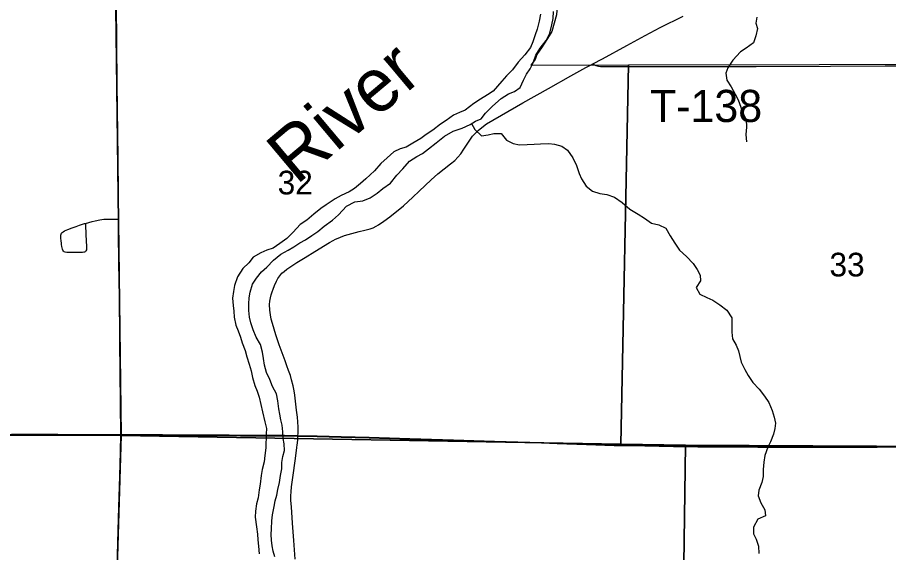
# Model space of a CAD drawing. Extents: x 0 to 34, y 0 to 22.
# Drawn here: x 4.194 to 4.964, y 17.65 to 18.123 of the extents above; entities that cross this region are included whole.
import ezdxf

# ---------------------------------------------------------------- set-up
doc = ezdxf.new("R2010")
doc.units = 0
for name, color, linetype in [('GM_X_Corporation', 7, 'Continuous'), ('GM_X_County_Road', 7, 'Continuous'), ('GM_X_Major_River', 7, 'Continuous'), ('GM_X_Major_River_Text', 7, 'Continuous'), ('GM_X_Minor_River', 7, 'Continuous'), ('GM_X_Section_Text', 7, 'Continuous'), ('GM_X_State_Route', 7, 'Continuous'), ('GM_X_Township_Road', 7, 'Continuous'), ('GM_X_Township_Road_Text', 7, 'Continuous')]:
    doc.layers.add(name, color=color, linetype=linetype)

msp = doc.modelspace()

# ---------------------------------------------------------------- linework, layer by layer
at = {"layer": 'GM_X_Corporation'}
for points in [[(3.77934, 18.25611), (4.27934, 18.22655), (4.28542, 17.75394), (3.7492, 17.7546)], [(4.27934, 18.22655), (4.66117, 18.20518), (4.66186, 18.19617), (4.66594, 18.18364), (4.67032, 18.16257), (4.67175, 18.15081), (4.67108, 18.13774), (4.67023, 18.12562), (4.66614, 18.11087), (4.66231, 18.10465), (4.65694, 18.09654), (4.65291, 18.09051), (4.65118, 18.08635), (4.64735, 18.08108), (4.73395, 18.08156), (4.72704, 17.74623), (4.28542, 17.75394)], [(5.2393, 18.08245), (5.23463, 17.74294), (4.78425, 17.74522), (4.72704, 17.74623), (4.73395, 18.08156)], [(4.28542, 17.75394), (4.27027, 17.25592), (3.73479, 17.25336), (3.7492, 17.7546)], [(4.72704, 17.74623), (4.78425, 17.74522), (4.77754, 17.26078), (4.56251, 17.2645), (4.54557, 17.25477), (4.27027, 17.25592), (4.28542, 17.75394)], [(5.26362, 17.74328), (5.26124, 17.2552), (4.77754, 17.26078), (4.78425, 17.74522), (5.23463, 17.74294)]]:
    msp.add_lwpolyline(points, close=True, dxfattribs=at)
for points in [[(4.97619, 17.74408), (4.9535, 17.74392), (4.942, 17.74382), (4.92615, 17.74385), (4.90564, 17.74379), (4.89569, 17.74385), (4.88201, 17.74392), (4.85995, 17.74394), (4.84814, 17.74397), (4.82265, 17.74401), (4.79499, 17.74422), (4.77354, 17.7445), (4.7608, 17.74479), (4.73563, 17.74518), (4.72103, 17.74543), (4.69648, 17.74623), (4.6707, 17.74707), (4.65704, 17.74753), (4.61541, 17.74867), (4.57907, 17.74986), (4.54056, 17.75104), (4.50452, 17.752), (4.47972, 17.75262), (4.4586, 17.7532), (4.4415, 17.75361), (4.4407, 17.75363), (4.42966, 17.75376), (4.41728, 17.75392), (4.40734, 17.75394), (4.39708, 17.75395), (4.39056, 17.75398), (4.38063, 17.75406), (4.3645, 17.75417), (4.35332, 17.75426), (4.33872, 17.75431), (4.32194, 17.75441), (4.29335, 17.75456), (4.28484, 17.75461), (4.27337, 17.75456), (4.25326, 17.75451), (4.24034, 17.75448), (4.22915, 17.75469), (4.20335, 17.75483), (4.18875, 17.75498)], [(4.18875, 17.75498), (4.20335, 17.75483), (4.22915, 17.75469), (4.24034, 17.75448), (4.25326, 17.75451), (4.27337, 17.75456), (4.28484, 17.75461), (4.29335, 17.75456), (4.32194, 17.75441), (4.33872, 17.75431), (4.35332, 17.75426), (4.3645, 17.75417), (4.38063, 17.75406), (4.39056, 17.75398), (4.39708, 17.75395), (4.40734, 17.75394), (4.41728, 17.75392), (4.42966, 17.75376), (4.4407, 17.75363), (4.4415, 17.75361), (4.4586, 17.7532), (4.47972, 17.75262), (4.50452, 17.752), (4.54056, 17.75104), (4.57907, 17.74986), (4.61541, 17.74867), (4.65704, 17.74753), (4.6707, 17.74707), (4.69648, 17.74623), (4.72103, 17.74543), (4.73563, 17.74518), (4.7608, 17.74479), (4.77354, 17.7445), (4.79499, 17.74422), (4.82265, 17.74401), (4.84814, 17.74397), (4.85995, 17.74394), (4.88201, 17.74392), (4.89569, 17.74385), (4.90564, 17.74379), (4.92615, 17.74385), (4.942, 17.74382), (4.9535, 17.74392), (4.97619, 17.74408)]]:
    msp.add_lwpolyline(points, dxfattribs=at)
at = {"layer": 'GM_X_County_Road'}
for points in [[(4.70234, 18.08224), (4.71083, 18.08667), (4.73233, 18.09849), (4.74868, 18.10747), (4.76188, 18.11443), (4.78217, 18.1246)], [(4.44161, 17.75333), (4.44165, 17.75625), (4.44172, 17.76119), (4.44148, 17.76581), (4.44105, 17.77014), (4.44044, 17.7763), (4.43951, 17.78433), (4.43882, 17.78955), (4.43823, 17.79322), (4.43733, 17.79777), (4.43601, 17.80318), (4.43487, 17.80703), (4.43335, 17.81142), (4.43186, 17.8155), (4.43022, 17.81986), (4.42845, 17.8245), (4.42672, 17.82916), (4.4249, 17.83413), (4.42336, 17.83854), (4.42191, 17.84297), (4.42042, 17.84772), (4.41902, 17.85283), (4.41802, 17.85676), (4.41728, 17.86044), (4.41661, 17.86472), (4.41644, 17.86974), (4.41677, 17.8727), (4.41718, 17.8755), (4.41792, 17.87829), (4.41874, 17.88093), (4.41965, 17.88323), (4.42096, 17.8866), (4.42261, 17.89022), (4.42384, 17.89261), (4.42548, 17.89507), (4.42746, 17.8973), (4.42926, 17.8989), (4.43165, 17.90083), (4.43432, 17.90262), (4.43782, 17.9049), (4.44059, 17.9067), (4.44805, 17.91117), (4.4565, 17.91641), (4.46944, 17.92439), (4.47268, 17.92624), (4.47474, 17.92741), (4.47704, 17.92839), (4.47934, 17.9293), (4.48267, 17.93058), (4.48921, 17.93243), (4.49571, 17.93407), (4.50072, 17.93523), (4.50541, 17.93654), (4.50821, 17.93753), (4.51059, 17.93877), (4.51289, 17.94016), (4.51742, 17.94321), (4.52276, 17.94727), (4.53486, 17.95684), (4.54302, 17.96442), (4.54885, 17.96996), (4.5594, 17.97995), (4.56536, 17.9852), (4.5764, 17.99387), (4.58016, 17.99708), (4.58301, 17.99989), (4.58556, 18.00295), (4.58835, 18.007), (4.59341, 18.01481), (4.59602, 18.01833), (4.59849, 18.02116), (4.60097, 18.02355), (4.60411, 18.02615), (4.60842, 18.02926), (4.64031, 18.04789), (4.66306, 18.06069), (4.68287, 18.07178), (4.69626, 18.07899), (4.70091, 18.08149), (4.70234, 18.08224)], [(3.74899, 17.75688), (3.77002, 17.75675), (3.79458, 17.75662), (3.8353, 17.75664), (3.84803, 17.75657), (3.86264, 17.75646), (3.90025, 17.75626), (3.95402, 17.75601), (3.99287, 17.75558), (4.02768, 17.75539), (4.09315, 17.75516), (4.11614, 17.75508), (4.12764, 17.75505), (4.13167, 17.75508), (4.14442, 17.75492), (4.1584, 17.7548), (4.17301, 17.75462), (4.18887, 17.75471), (4.20346, 17.75455), (4.22926, 17.75441), (4.24045, 17.7542), (4.25337, 17.75423), (4.27348, 17.75428), (4.28495, 17.75434)], [(4.28495, 17.75434), (4.29346, 17.75429), (4.32205, 17.75413), (4.33883, 17.75404), (4.35344, 17.75398), (4.36461, 17.75389), (4.38074, 17.75378), (4.39067, 17.7537), (4.3972, 17.75367), (4.40745, 17.75367), (4.41739, 17.75364), (4.42977, 17.75349), (4.44082, 17.75335), (4.44161, 17.75333)], [(4.44161, 17.75333), (4.45871, 17.75292), (4.47983, 17.75234), (4.50463, 17.75172), (4.54067, 17.75076), (4.57919, 17.74959), (4.61553, 17.7484), (4.65715, 17.74726), (4.67081, 17.74679), (4.69659, 17.74595), (4.72114, 17.74515), (4.73574, 17.7449), (4.76091, 17.74451), (4.77366, 17.74422), (4.7951, 17.74394), (4.82277, 17.74374), (4.84825, 17.7437), (4.86006, 17.74366), (4.88212, 17.74365), (4.8958, 17.74357), (4.90575, 17.74352), (4.92626, 17.74357), (4.94211, 17.74354), (4.95361, 17.74365), (4.9763, 17.7438)]]:
    msp.add_lwpolyline(points, dxfattribs=at)
at = {"layer": 'GM_X_Major_River'}
for points in [[(4.65613, 18.12639), (4.65496, 18.12013), (4.65321, 18.11312), (4.65128, 18.10801), (4.64935, 18.10175), (4.64723, 18.09683), (4.64208, 18.09041), (4.63636, 18.0838), (4.6312, 18.077), (4.62605, 18.0719), (4.62185, 18.06699), (4.61422, 18.0583), (4.60928, 18.05511), (4.603, 18.05116), (4.59711, 18.0474), (4.5893, 18.04137), (4.58437, 18.0395), (4.57924, 18.03687), (4.57277, 18.03216), (4.56764, 18.02916), (4.56078, 18.02369), (4.55508, 18.01993), (4.55032, 18.01635), (4.5431, 18.01222), (4.5372, 18.00884), (4.53189, 18.00735), (4.52638, 18.00453), (4.52048, 17.99944), (4.51476, 17.99416), (4.50923, 17.98774), (4.50161, 17.98076), (4.49685, 17.97661), (4.49152, 17.97228), (4.48676, 17.96927), (4.47992, 17.96589), (4.47441, 17.96308), (4.46661, 17.95781), (4.46167, 17.95442), (4.45558, 17.94952), (4.44929, 17.94406), (4.44359, 17.94029), (4.43748, 17.9335), (4.43177, 17.92802), (4.42568, 17.9235), (4.41978, 17.91955), (4.41409, 17.91769), (4.40877, 17.91544), (4.40212, 17.9115), (4.39811, 17.90658), (4.39277, 17.90149), (4.38818, 17.89411), (4.38548, 17.88635), (4.3845, 17.88104), (4.38371, 17.87516), (4.38423, 17.86889), (4.38477, 17.86376), (4.3853, 17.85844), (4.38659, 17.85141), (4.38864, 17.84647), (4.39087, 17.84076), (4.39236, 17.83581), (4.39497, 17.82915), (4.39645, 17.82326), (4.39849, 17.81679), (4.40016, 17.8109), (4.40145, 17.8052), (4.40348, 17.79797), (4.40554, 17.79302), (4.40721, 17.7877)], [(4.4293, 17.74638), (4.42857, 17.75132), (4.42823, 17.75701), (4.4277, 17.7629), (4.42659, 17.76765), (4.42548, 17.77259), (4.42457, 17.77735), (4.42366, 17.78437), (4.42257, 17.79084), (4.41901, 17.79731), (4.41659, 17.8034), (4.41379, 17.80968), (4.41212, 17.81595), (4.41102, 17.82204), (4.41011, 17.82755), (4.40845, 17.83439), (4.4047, 17.84086), (4.4019, 17.84734), (4.39986, 17.85342), (4.39875, 17.85836), (4.39803, 17.86444), (4.39807, 17.87014), (4.39848, 17.87564), (4.39946, 17.88057), (4.4014, 17.88777), (4.40503, 17.89306), (4.40923, 17.89854), (4.41399, 17.90269), (4.42009, 17.90892), (4.42638, 17.9142), (4.43284, 17.91777), (4.43797, 17.92059), (4.4433, 17.92416), (4.44824, 17.92679), (4.45394, 17.93055), (4.45908, 17.93413), (4.46479, 17.93903), (4.47202, 17.9443), (4.47754, 17.94902), (4.4846, 17.95657), (4.49182, 17.96032), (4.49883, 17.96142), (4.50548, 17.96385), (4.51176, 17.96818), (4.51671, 17.97232), (4.52355, 17.97703), (4.52909, 17.98402), (4.53443, 17.98949), (4.54034, 17.99648), (4.54662, 18.00043), (4.55175, 18.00306), (4.55708, 18.0072), (4.56393, 18.01248), (4.57117, 18.01851), (4.57877, 18.02283), (4.58674, 18.02563), (4.59377, 18.02881), (4.59852, 18.03182), (4.60346, 18.03388), (4.60747, 18.03879), (4.61357, 18.04502), (4.62119, 18.05162), (4.62785, 18.05595), (4.63316, 18.058), (4.63792, 18.06139), (4.64099, 18.06783), (4.64367, 18.07313), (4.64693, 18.07804), (4.64942, 18.08334), (4.65193, 18.09016), (4.65575, 18.09621), (4.66091, 18.10301), (4.66417, 18.10945), (4.66611, 18.11684), (4.6671, 18.12253), (4.66751, 18.1286)], [(4.40721, 17.7877), (4.40887, 17.78123), (4.41035, 17.77477), (4.41219, 17.76603), (4.41366, 17.76013), (4.41345, 17.75539), (4.41318, 17.74286), (4.41238, 17.73622), (4.41158, 17.73053), (4.41003, 17.7239), (4.40905, 17.71859), (4.40824, 17.71081), (4.40726, 17.70588), (4.40627, 17.69886), (4.40491, 17.69356), (4.40412, 17.68711), (4.40389, 17.6816), (4.40497, 17.67305), (4.40569, 17.66659), (4.40604, 17.66166), (4.40657, 17.65615), (4.40729, 17.64931)], [(4.4211, 17.64676), (4.41961, 17.65152), (4.4187, 17.65646), (4.41816, 17.6614), (4.41781, 17.66652), (4.41822, 17.67127), (4.41846, 17.67848), (4.41906, 17.68379), (4.42043, 17.691), (4.42141, 17.69612), (4.42295, 17.70123), (4.42374, 17.70616), (4.4253, 17.71242), (4.42628, 17.71849), (4.42727, 17.72437), (4.4273, 17.72987), (4.42809, 17.73518), (4.42964, 17.74068), (4.4293, 17.74638)]]:
    msp.add_lwpolyline(points, dxfattribs=at)
at = {"layer": 'GM_X_Minor_River'}
for points in [[(4.84741, 18.12356), (4.84643, 18.11825), (4.84791, 18.11349), (4.84636, 18.10705), (4.84443, 18.10099), (4.83796, 18.09609), (4.83301, 18.09289), (4.82615, 18.08572), (4.82175, 18.07891), (4.81982, 18.07399), (4.82092, 18.06791), (4.82448, 18.06219), (4.82823, 18.05553), (4.83066, 18.05058), (4.83308, 18.04411), (4.83494, 18.03897), (4.83774, 18.03307), (4.83808, 18.02643), (4.83766, 18.01979), (4.83819, 18.01333)], [(4.59505, 18.02962), (4.59791, 18.02423), (4.60394, 18.01888), (4.60981, 18.01961), (4.61474, 18.02091), (4.62137, 18.02087), (4.62588, 18.01496), (4.63173, 18.01208), (4.63741, 18.01071), (4.64423, 18.01106), (4.65048, 18.0114), (4.65616, 18.01174), (4.66336, 18.01208), (4.66847, 18.01129), (4.6749, 18.00955), (4.6798, 18.0061), (4.68468, 17.99924), (4.68786, 17.99258), (4.69028, 17.98554), (4.69233, 17.98078), (4.69627, 17.9743), (4.70211, 17.96971), (4.70854, 17.96778), (4.71478, 17.96679), (4.72159, 17.96447), (4.72819, 17.95969), (4.73516, 17.95395), (4.74232, 17.94936), (4.74799, 17.9461), (4.75421, 17.9415), (4.76064, 17.94014), (4.76687, 17.93706), (4.7708, 17.93021), (4.77474, 17.92392), (4.77906, 17.91763), (4.78508, 17.91209), (4.79091, 17.90579), (4.79467, 17.90045), (4.79729, 17.89569), (4.79745, 17.89057), (4.79381, 17.8847), (4.79699, 17.8788), (4.80323, 17.87573), (4.80832, 17.87342), (4.81455, 17.8694), (4.82077, 17.86461), (4.82527, 17.85775), (4.82519, 17.84523), (4.82572, 17.83934), (4.8291, 17.83381), (4.83115, 17.82868), (4.83226, 17.82373), (4.83355, 17.81879), (4.83673, 17.81213), (4.83954, 17.80698), (4.84366, 17.8007), (4.8495, 17.79497), (4.8542, 17.78868), (4.85795, 17.78296), (4.86074, 17.77592), (4.8626, 17.77002), (4.86371, 17.76489), (4.86311, 17.76015), (4.86213, 17.75503), (4.85925, 17.7484), (4.85713, 17.74348), (4.85443, 17.73609), (4.85345, 17.73021), (4.85303, 17.72395), (4.8528, 17.71769), (4.85163, 17.71238), (4.84913, 17.70556), (4.84834, 17.70044), (4.85076, 17.69435), (4.85432, 17.68806), (4.85486, 17.68294), (4.84821, 17.67994), (4.84438, 17.67294), (4.84434, 17.66705), (4.84677, 17.66229), (4.84882, 17.65601), (4.84897, 17.64956)]]:
    msp.add_lwpolyline(points, dxfattribs=at)
at = {"layer": 'GM_X_State_Route'}
for points in [[(4.28495, 17.75434), (4.2847, 17.78307), (4.28404, 17.83703), (4.28368, 17.88024), (4.28332, 17.90541), (4.28302, 17.93431), (4.28296, 17.94523), (4.28283, 17.96757), (4.28248, 17.99926), (4.28234, 18.02008), (4.28186, 18.06515), (4.28154, 18.09965), (4.28121, 18.13602)], [(4.28202, 17.64809), (4.2827, 17.66981), (4.28329, 17.69063), (4.28395, 17.71797), (4.28455, 17.73939), (4.28495, 17.75434)]]:
    msp.add_lwpolyline(points, dxfattribs=at)
at = {"layer": 'GM_X_Township_Road'}
for points in [[(4.70234, 18.08224), (4.70329, 18.08175), (4.70501, 18.08093), (4.70723, 18.08035), (4.70921, 18.08003), (4.71118, 18.08003), (4.71783, 18.07988), (4.75078, 18.08005), (4.79119, 18.08008), (4.84683, 18.08013), (4.91242, 18.08026), (4.96091, 18.08054), (4.9927, 18.0806)], [(4.25371, 17.94132), (4.25379, 17.9389), (4.25386, 17.93691), (4.25394, 17.93471), (4.2541, 17.93161), (4.25464, 17.92074), (4.25466, 17.91888), (4.25452, 17.91796), (4.25416, 17.9171), (4.25379, 17.91661), (4.25332, 17.91621), (4.25276, 17.91594), (4.25217, 17.91577), (4.25094, 17.91563), (4.24628, 17.91568), (4.23944, 17.91564), (4.23725, 17.91566), (4.23572, 17.91587), (4.23487, 17.91623), (4.23417, 17.91679), (4.23365, 17.91755), (4.23332, 17.91843), (4.23303, 17.91964), (4.23288, 17.92085), (4.23266, 17.92269), (4.2325, 17.9239), (4.23221, 17.92593), (4.23186, 17.9284), (4.23179, 17.92995), (4.23188, 17.93088), (4.23213, 17.93177), (4.23255, 17.9326), (4.23314, 17.93332), (4.23387, 17.93388), (4.23524, 17.93463), (4.23807, 17.93589), (4.24184, 17.93732), (4.24535, 17.93859), (4.24855, 17.93975), (4.25298, 17.94112), (4.25371, 17.94132)], [(4.25371, 17.94132), (4.25952, 17.94296), (4.26223, 17.94364), (4.26647, 17.94454), (4.26985, 17.94496), (4.27325, 17.94516), (4.27818, 17.94522), (4.2797, 17.94523), (4.28296, 17.94523)], [(4.43914, 17.64455), (4.43796, 17.66098), (4.43685, 17.67648), (4.43575, 17.69074), (4.43541, 17.6963), (4.43536, 17.70062), (4.4355, 17.70401), (4.43597, 17.70863), (4.43694, 17.71664), (4.43931, 17.73362), (4.44065, 17.74326), (4.44097, 17.74569), (4.44107, 17.74717), (4.44137, 17.75028), (4.44161, 17.75333)]]:
    msp.add_lwpolyline(points, dxfattribs=at)

# ---------------------------------------------------------------- texts
at = {"layer": 'GM_X_Major_River_Text'}
msp.add_text('River', height=0.047371, rotation=40.01362, dxfattribs=at).set_placement((4.44011, 17.97461))
at = {"layer": 'GM_X_Section_Text'}
for s, p in [('32', (4.42361, 17.96696)), ('33', (4.91152, 17.89446))]:
    msp.add_text(s, height=0.020928, rotation=0.00001, dxfattribs=at).set_placement(p)
at = {"layer": 'GM_X_Township_Road_Text'}
msp.add_text('T-138', height=0.028409, rotation=0.00001, dxfattribs=at).set_placement((4.75277, 18.03095))

doc.saveas('drawing.dxf')
